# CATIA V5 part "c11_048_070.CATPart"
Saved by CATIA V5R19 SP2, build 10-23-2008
Part number: cageBille
Definition: NONE
Nomenclature: 1
Source: Unknown
Description: PART-1-DESC
Bounding box of the stored display mesh (mm): x -27.15 to 27.15, y 25 to 45, z -27.15 to 27.15
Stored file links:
  D:\SCHOOL\FRANCE\BANC_POUTRE_EN_MOUSSE\c11_048_070.CATPart
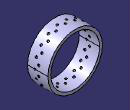
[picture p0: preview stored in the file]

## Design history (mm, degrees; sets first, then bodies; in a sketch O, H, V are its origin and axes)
AxisSystem1: origin (0, 0, 0), X (1, 0, 0), Y (0, 1, 0), Z (0, 0, 1)
Set1
  Sketch1 on face of Solid1, origin (0, 70, 0), H (-1, 0, 0), V (0, 0, 1)
    circle A1 centre (0, 0) radius 39.7133
Body1 "1" (main body)
  Solid1: solid without history
  Pocket1: profile Sketch1, direction (0, -1, 0), length 25
  Sketch2 on face of Solid1, origin (0, 0, 0), H (1, 0, 0), V (0, 0, 1)
    circle A1 centre (0, 0) radius 31.1931
  Pocket2: profile Sketch2, direction (0, 1, 0), length 25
